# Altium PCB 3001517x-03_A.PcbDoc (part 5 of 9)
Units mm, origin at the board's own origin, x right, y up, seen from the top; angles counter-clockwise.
Board outline 100 x 72 mm, 10 copper layers (Top, GND_2, Signal_3, Signal_4, PWR_5, GND_6, Signal_7, Signal_8, GND_9, Bottom), stack 1.6 mm thick; 602 components, 497 nets, 2372 pads, 1602 vias.
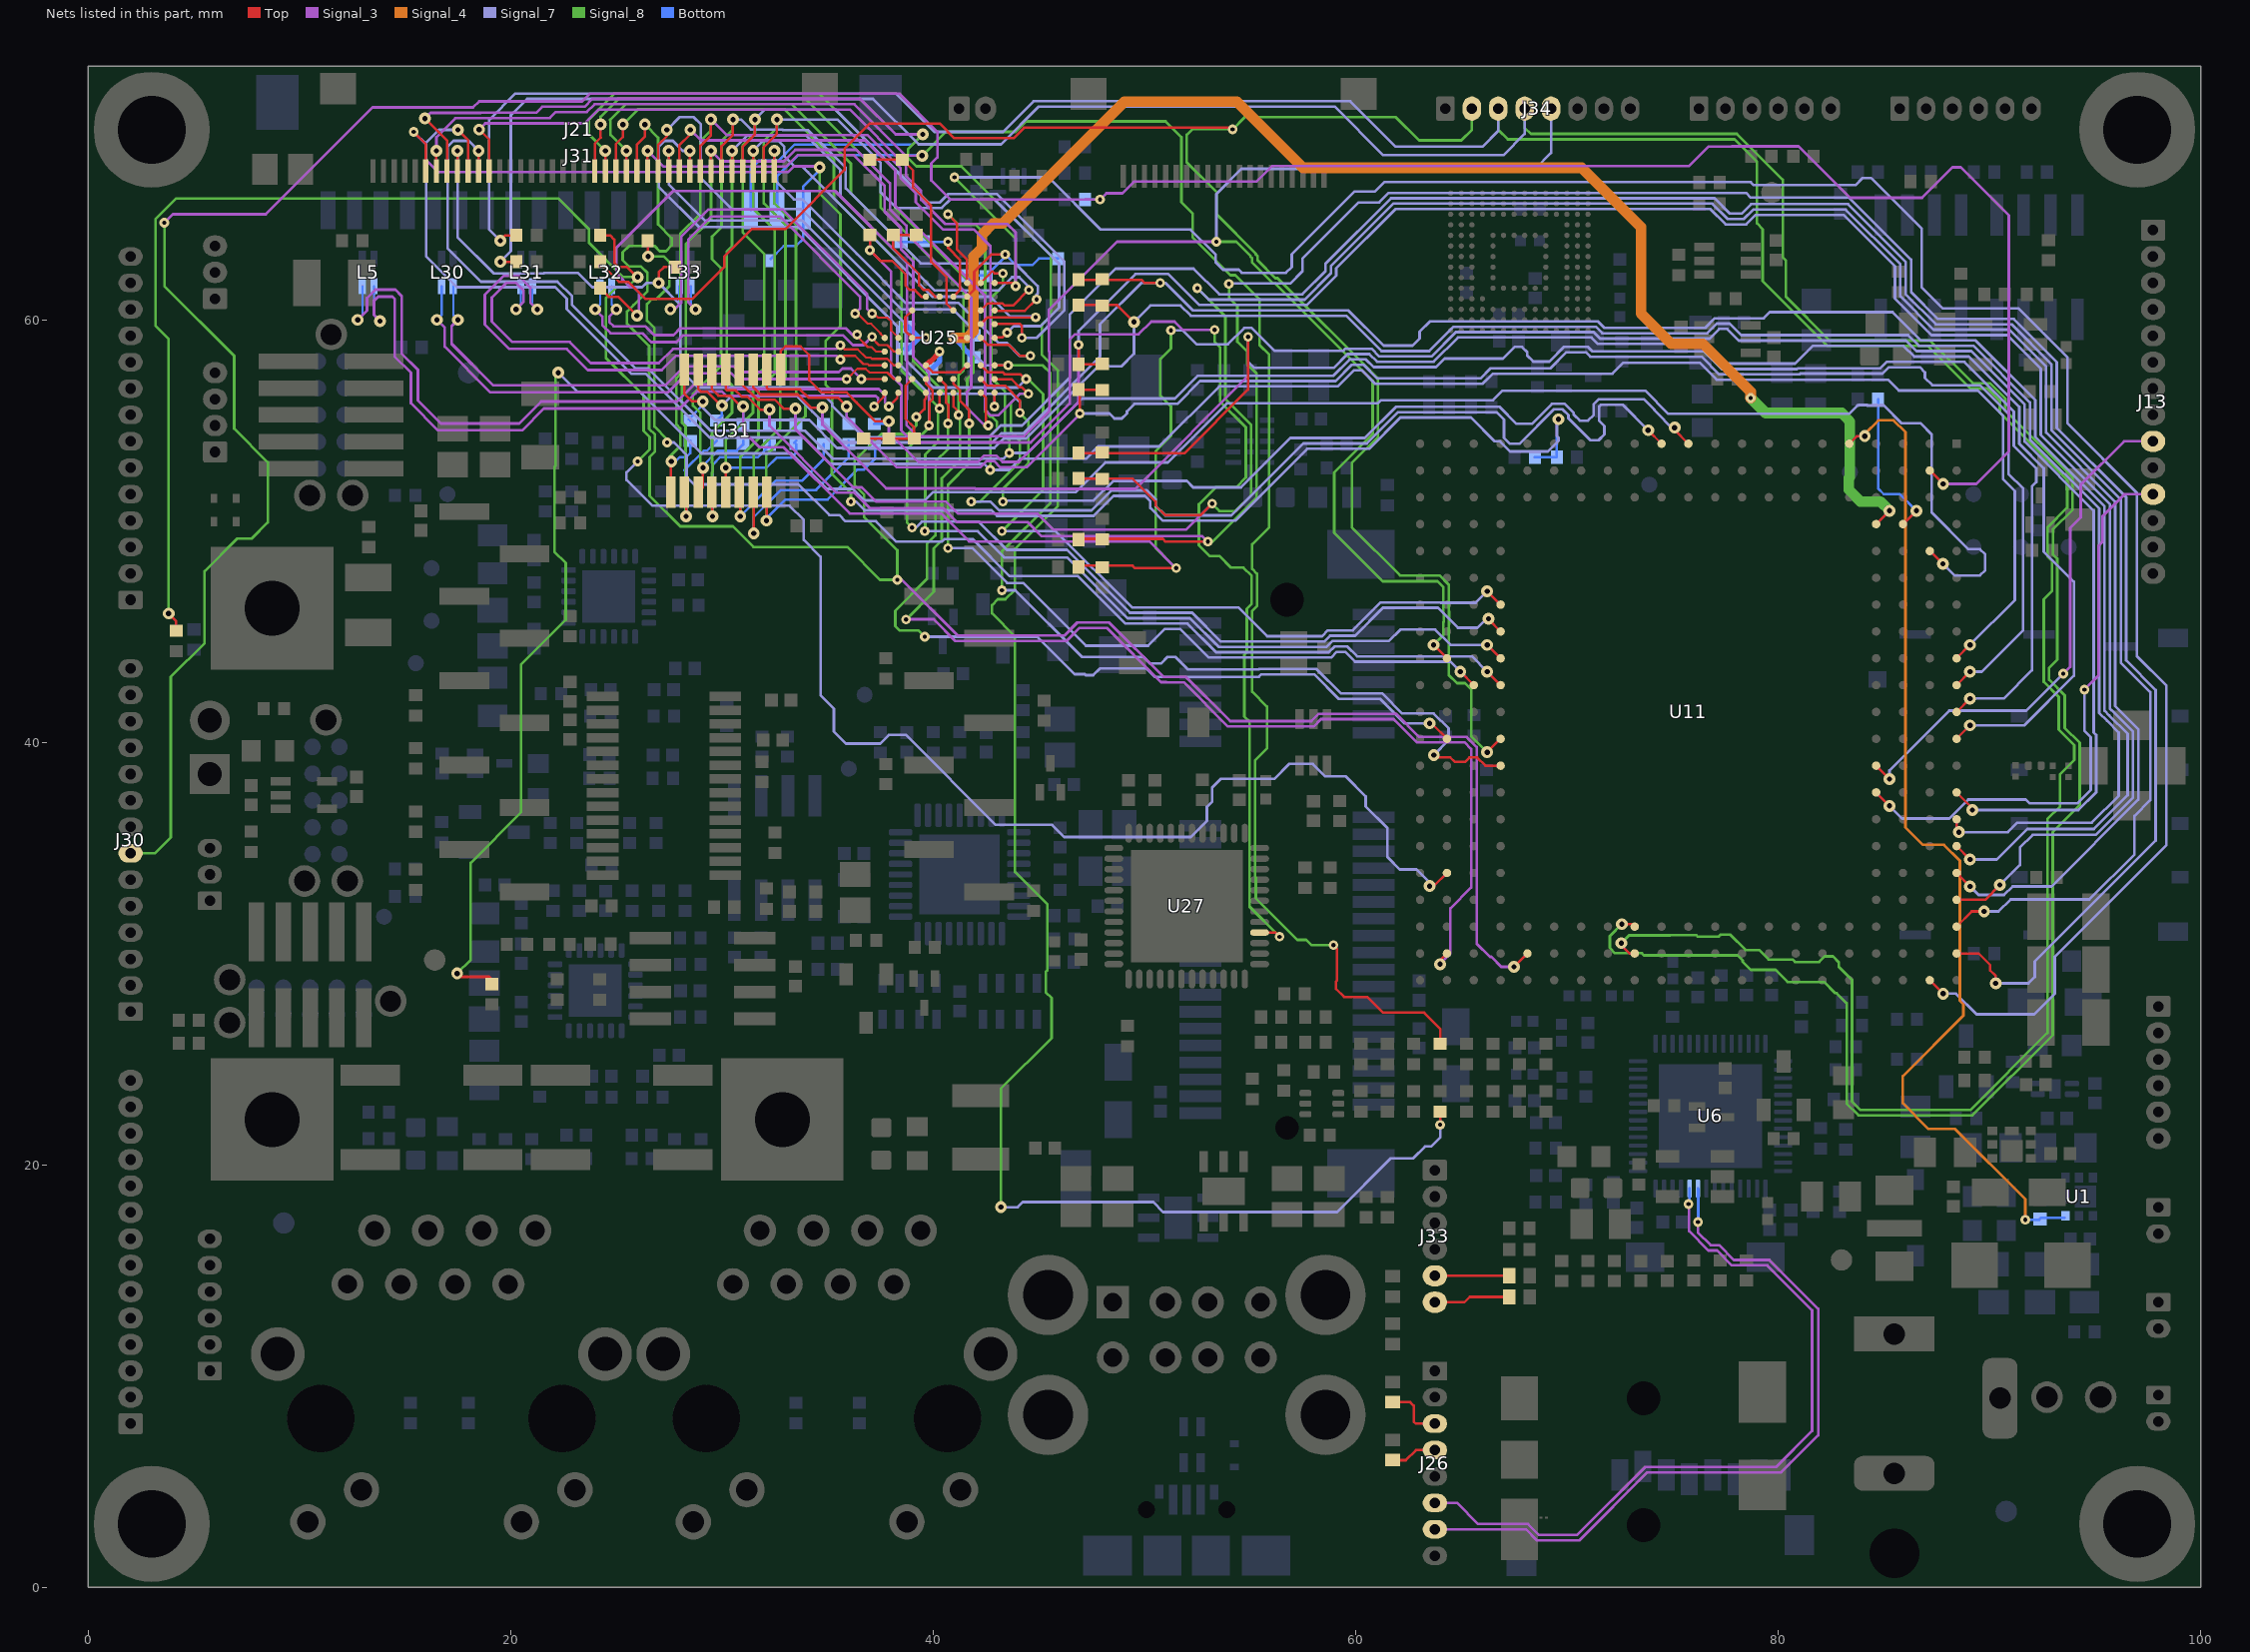
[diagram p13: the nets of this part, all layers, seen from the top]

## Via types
v1: diameter 0.56, hole 0.25, Top to Bottom, tented both sides, 1002 vias
v2: diameter 0.46, hole 0.2, Top to Bottom, tented both sides, 468 vias
v3: diameter 0.457, hole 0.2, Top to Bottom, tented both sides, 132 vias

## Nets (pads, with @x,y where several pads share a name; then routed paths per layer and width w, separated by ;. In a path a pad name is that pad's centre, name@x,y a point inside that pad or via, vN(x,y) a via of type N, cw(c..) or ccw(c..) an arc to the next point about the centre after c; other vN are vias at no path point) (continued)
LCD_DATA0: R112.2 R214.1 R222.1 U11.A18 U31.2 | length 112.7
  Top w0.119: U31.2@32.775,57.65 32.775,58.525 33,58.75 33.713,58.75 34.125,58.338 34.125,57.149 34.712,56.562 35.897,56.562 36.366,56.093 37.26,55.2 v1(37.9,55.2) ; v2(46.88,58.82) R222.1@46.88,57.9 47.98,57.9 R112.2@48,57.92 ; U11.A18@88.45,32.55 89.8,32.55 v1(90.5,33.25)
  Signal_3 w0.127: v1(37.9,55.2) 37.9,54.671 39.297,53.274 42.121,53.274 42.421,53.575 42.979,53.575 43.279,53.274 44.05,53.274 46.88,56.105 v2(46.88,58.82)
  Signal_7 w0.127: v2(46.88,58.82) 46.88,59.48 49.571,62.171 51.13,62.171 52.597,60.703 57.687,60.703 59.079,62.095 59.079,62.445 61.884,65.25 76.779,65.25 77.508,64.522 78.483,64.522 78.932,64.97 83.095,64.97 85.53,62.535 85.53,61.009 87.256,59.282 90.84,59.282 92.431,57.691 92.431,54.559 95.705,51.285 95.705,41.602 95.779,41.528 95.784,41.528 96.8,40.513 96.8,37.397 95.028,35.625 92.06,35.625 91.45,35.015 91.45,34.2 v1(90.5,33.25)
  Bottom w0.119: R214.1@37.208,55.08 37.88,55.08 37.9,55.1 v1(37.9,55.2)
LCD_DATA0_PROT: J21.2 R214.2 U25.H5 U31.18 | length 48.1
  Top w0.119: v1(32.1,50.5) 32.125,50.525 U31.18@32.125,51.85 ; J21.2@32.476,67.05 v1(32.476,68.007) ; U25.H5@42.25,59.15 42.575,58.825 43.571,58.825 44.096,58.3 v2(44.6,58.3)
  Signal_8 w0.127: v1(32.1,50.5) 32.1,53.6 33.945,55.445 33.945,55.995 33.504,56.436 33.504,59.62 33.496,59.628 33.496,64.504 32.476,65.524 v1(32.476,68.007)
  Signal_7 w0.127: v1(32.476,68.007) 32.476,66.624 33.4,65.7 33.8,65.7 36.374,63.126 38.7,60.8 41.2,60.8 43.08,58.92 43.476,58.92 44.096,58.3 v2(44.6,58.3)
  Bottom w0.119: v1(32.1,50.5) 32.1,50.6 33,51.5 35,51.5 36.415,52.915 36.715,52.915 37.25,53.45 R214.2@37.25,54.27
LCD_DATA1: R113.2 R215.1 R233.1 U11.A10 U31.3 | length 84.4
  Top w0.119: U31.3@32.125,57.65 U31.3@32.125,57.061 ; U31.3@32.173,57.013 U31.3@32.125,57.061 ; v1@36,55.8 v1(35.9,55.9) 35.484,56.316 34.091,56.316 33.694,56.713 32.187,56.713 32.125,56.775 U31.3@32.125,57.061 ; v2(46.935,55.565) 46.935,56.645 R233.1@46.88,56.7 47.98,56.7 R113.2@48,56.68 ; U11.A10@88.45,42.71 v1(89.085,43.345)
  Signal_3 w0.127: v1(35.9,55.9) 35.9,55.4 38.28,53.02 42.226,53.02 42.526,53.321 42.874,53.321 43.174,53.02 44.426,53.02 46.935,55.53 v2(46.935,55.565)
  Signal_7 w0.127: v2(46.935,55.565) 48.34,55.565 48.576,55.33 48.924,55.33 49.17,55.576 49.17,55.67 49.526,56.026 51.55,56.026 52.631,57.106 59.052,57.106 59.821,57.874 60.379,57.874 61.024,57.229 65.906,57.229 66.386,57.709 69.209,57.709 69.97,58.47 70.895,58.47 71.111,58.254 76.387,58.254 77.219,57.422 81.005,57.422 81.041,57.457 84.94,57.457 85.241,57.758 86.705,57.758 86.951,57.512 86.951,57.254 87.298,56.907 89.56,56.907 90.907,55.56 90.907,52.718 91.6,52.025 91.6,45.3 89.645,43.345 v1(89.085,43.345)
  Bottom w0.119: v1(35.9,55.9) 35.9,55.33 R215.1@36,55.23
LCD_DATA1_PROT: J21.3 R215.2 U25.J5 U31.17 | length 55.8
  Top w0.119: U31.17@31.475,51.85 31.5,51.825 v1(31.5,49.9) ; J21.3@31.976,67.05 31.976,68.181 32.599,68.804 v1(32.599,69.485) ; U25.J5@42.9,59.15 42.912,59.162 43.262,59.162 v2(43.5,59.4)
  Signal_8 w0.127: v1(31.5,49.9) 31.5,53.635 32.75,54.885 32.75,56.968 33,57.218 33,64.5 31.976,65.524 31.976,68.476 32.599,69.099 v1(32.599,69.485)
  Signal_7 w0.127: v1(32.599,69.485) 35.466,69.485 37.5,67.451 37.5,66.054 38.25,65.304 40.409,65.304 40.803,65.698 42.91,65.698 45.953,62.654 45.953,60.578 45.08,59.705 43.804,59.705 v2(43.5,59.4)
  Bottom w0.119: v1(31.5,49.9) 31.5,50.664 32.786,51.95 34.45,51.95 36,53.5 R215.2@36,54.12 R215.2@36,54.27
LCD_DATA2: R147.2 R216.1 R234.1 U11.A12 U31.4 | length 104.8
  Top w0.119: U31.4@31.475,57.65 31.475,56.821 31.828,56.467 33.592,56.467 34.21,55.85 v1(34.75,55.85) ; R234.1@46.88,53.7 51.906,53.7 54.9,56.694 v2(54.9,59.2) ; R147.2@48,53.72 R147.2@48.165,53.885 ; U11.A12@88.45,40.17 v1(89.085,40.805)
  Signal_3 w0.127: v1(34.75,55.85) 34.75,55.043 37.772,52.021 41.974,52.021 41.995,52 49.565,52 54.9,57.335 v2(54.9,59.2)
  Signal_7 w0.127: v2(54.9,59.2) 54.9,58.034 55.205,57.729 58.957,57.729 59.61,58.382 60.645,58.382 61.01,58.018 63.693,58.018 64.845,59.169 71.159,59.169 71.467,58.861 76.6,58.861 77.532,57.93 80.795,57.93 81.636,58.77 85.943,58.77 86.447,58.266 89.034,58.266 91.415,55.885 91.415,54.139 92.575,52.979 92.575,49.025 94,47.6 94,43.155 91.65,40.805 v1(89.085,40.805)
  Bottom w0.119: R216.1@34.75,55.23 v1(34.75,55.85)
LCD_DATA2_PROT: J21.4 R216.2 U25.H6 U31.16 | length 46.3
  Top w0.119: U31.16@30.825,51.85 30.863,51.812 v1(30.863,50.7) ; J21.4@31.476,67.05 v1(31.476,68.007) ; U25.H6@42.25,59.8 42.575,60.125 v2(44.85,60.125)
  Signal_8 w0.127: v1(30.863,50.7) 30.863,53.513 31.724,54.375 31.724,56.692 32.496,57.463 32.496,59.62 32.5,59.624 32.5,64.25 31.476,65.274 v1(31.476,68.007)
  Signal_7 w0.127: v1(31.476,68.007) 31.947,68.477 32.671,68.477 32.947,68.202 32.947,67.753 33.429,67.271 33.795,67.271 34.07,66.995 34.07,66.989 39.959,61.1 42.7,61.1 43.646,60.154 44.821,60.154 v2(44.85,60.125)
  Bottom w0.119: v1(30.863,50.7) 32.563,52.4 33.8,52.4 34.8,53.4 R216.2@34.8,54.12
LCD_DATA3: R153.2 R217.1 R235.1 U11.A17 U31.5 | length 128.2
  Top w0.119: U31.5@30.825,57.65 30.825,57.061 31.274,56.612 31.295,56.612 31.686,56.222 32.496,56.222 32.917,55.8 v1(33.475,55.8) ; R235.1@46.88,52.5 46.9,52.48 R153.2@48,52.48 49.444,52.48 50.533,51.391 50.533,51.207 50.99,50.75 52.65,50.75 v2(53.2,51.3) ; U11.A17@88.45,33.82 v1(89.085,33.185)
  Signal_3 w0.127: v1(33.475,55.8) 33.475,54.825 36.226,52.074 36.618,52.074 37.292,51.4 40.6,51.4 41.174,50.826 44.937,50.826 45.683,50.08 51.979,50.08 v2(53.2,51.3)
  Signal_8 w0.127: v2(52.5,61.5) 53.832,60.168 53.832,56.245 55.054,55.024 55.054,51.689 54.315,50.95 53.55,50.95 v2(53.2,51.3)
  Signal_7 w0.127: v2(52.5,61.5) 53.043,60.957 57.582,60.957 58.825,62.2 58.825,62.55 61.779,65.504 76.884,65.504 77.613,64.776 78.378,64.776 78.827,65.224 83.2,65.224 85.784,62.641 85.784,61.114 87.362,59.536 90.945,59.536 92.685,57.797 92.685,54.665 95.959,51.39 95.959,41.713 97.054,40.618 97.054,37.68 97.054,37.291 92.948,33.185 91.1,33.185 90.695,32.78 89.491,32.78 v1(89.085,33.185)
  Bottom w0.119: v1(33.475,55.8) 33.475,55.255 R217.1@33.5,55.23
LCD_DATA3_PROT: J21.5 R217.2 U25.J6 U31.15 | length 50.8
  Top w0.119: U31.15@30.175,51.85 v1(30.175,53.007) ; J21.5@30.976,67.05 30.976,68.202 31.558,68.783 v1(31.558,69.485) ; U25.J6@42.9,59.8 42.917,59.816 44.084,59.816 44.2,59.7 v2(44.2,59.15)
  Signal_8 w0.127: v1(30.175,53.007) 30.175,54.31 31.47,55.605 31.47,57.22 32,57.75 32,63.118 30.976,64.142 30.976,68.274 31.558,68.855 v1(31.558,69.485)
  Signal_7 w0.127: v1(31.558,69.485) 32.028,69.956 35.355,69.956 39.753,65.558 40.304,65.558 40.698,65.952 43.016,65.952 46.207,62.76 46.207,60.467 44.891,59.15 v2(44.2,59.15)
  Bottom w0.119: v1(30.175,53.007) 32.115,53.007 32.582,53.473 33.276,53.473 33.5,53.697 R217.2@33.5,54.12 ; R217.2@33.425,54.195 R217.2@33.5,54.27
LCD_DATA4: R17.1 R218.1 R238.2 U11.A20 U31.6 | length 131.8
  Top w0.119: U31.6@30.175,57.65 30.175,56.725 30.241,56.659 30.641,56.659 30.933,56.366 31.193,56.366 31.81,55.75 v1(32.25,55.75) ; R17.1@46.88,49.6 46.915,49.635 50.865,49.635 51,49.5 v2(53,49.5) ; U11.A20@88.45,30.01 89.49,30.01 90.034,29.466 90.034,29.207 90.3,28.94 v1(90.3,28.6)
  Signal_3 w0.127: v1(32.25,55.75) 32.25,54.993 35.423,51.82 36.274,51.82 37.005,51.089 40.474,51.089 41.143,50.42 44.48,50.42 45.136,49.764 52.736,49.764 v2(53,49.5)
  Signal_8 w0.127: v2(53,49.5) 53.225,49.5 55.308,51.583 55.308,57.457 54.87,57.895 54.87,58.495 54.4,58.965 54.4,60.654 54,61.054 v2(54,61.7)
  Signal_7 w0.127: v2(54,61.7) 54,61.625 54.096,61.721 56.905,61.721 57.478,62.295 57.478,62.894 60.147,65.562 61.118,65.562 61.568,66.012 78.488,66.012 78.708,65.792 83.351,65.792 86.292,62.851 86.292,61.324 87.572,60.044 91.156,60.044 93.193,58.007 93.193,54.893 96.477,51.609 96.477,43.88 97.875,42.481 97.875,35.351 92.152,29.627 92.152,28.898 91.853,28.6 v1(90.3,28.6)
  Bottom w0.119: R218.1@32.25,55.03 v1(32.25,55.75)
LCD_DATA4_PROT: J21.6 R218.2 U25.H7 U31.14 | length 47.3
  Top w0.119: U31.14@29.525,51.85 29.55,51.825 v1(29.55,50.7) ; J21.6@30.476,67.05 v1(30.476,68.007) ; U25.H7@42.25,60.45 42.589,60.789 43.272,60.789 43.377,60.684 43.784,60.684 v2(44.525,61.425)
  Signal_8 w0.127: v1(29.55,50.7) 29.529,50.721 29.529,52.764 29.57,52.805 29.57,53.195 29.529,53.236 29.529,54.664 30.47,55.605 30.47,55.752 ; 30.471,55.752 30.471,56.904 30.225,57.15 30.225,63.225 30.476,63.476 v1(30.476,68.007)
  Signal_7 w0.127: v1(30.476,68.007) 31.201,68.731 33.969,68.731 35.6,67.1 35.6,65.855 40.055,61.4 43.105,61.4 43.726,62.02 44.074,62.02 44.525,61.569 v2(44.525,61.425)
  Bottom w0.119: v1(29.55,50.7) 29.566,50.716 29.566,53.166 29.9,53.5 31.7,53.5 32.25,54.05 R218.2@32.25,54.27
LCD_DATA5: R156.2 R219.1 R236.1 U11.A14 U31.7 | length 116.2
  Top w0.119: U31.7@29.7,57.475 U31.7@29.525,57.65 29.525,56.715 29.827,56.413 30.387,56.413 30.9,55.9 v1(31,55.9) ; R236.1@46.88,48.3 46.88,48.4 46.9,48.38 48,48.38 48.015,48.365 49.44,48.365 49.555,48.25 v2(51.5,48.25) ; U11.A14@88.45,37.63 89.2,36.88 v1(89.2,36.8)
  Signal_3 w0.127: v1(31,55.9) 31,54.75 31.777,53.973 32.911,53.973 36.048,50.835 40.368,50.835 41.694,49.51 50.24,49.51 v2(51.5,48.25)
  Signal_8 w0.127: v2(51.25,59.5) 51.25,58.65 50.75,58.15 50.75,56.408 51.25,55.908 51.25,54.503 50.529,53.782 50.529,49.221 v2(51.5,48.25)
  Signal_7 w0.127: v2(51.25,59.5) 51.811,59.5 52.464,58.847 53.952,58.847 54.726,59.62 55.074,59.62 56.165,58.529 59.398,58.529 59.505,58.636 60.75,58.636 61.115,58.272 63.588,58.272 64.739,59.423 71.264,59.423 71.572,59.115 76.75,59.115 77.205,59.571 77.595,59.571 78.141,59.024 86.048,59.024 86.552,58.52 89.139,58.52 91.669,55.99 91.669,54.244 94.943,50.97 94.943,40.462 95.054,40.351 95.054,37.637 94.217,36.8 v1(89.2,36.8)
  Bottom w0.119: R219.1@31,55.23 v1(31,55.9)
LCD_DATA5_PROT: J21.7 R219.2 U25.J7 U31.13 | length 45.3
  Top w0.119: U31.13@28.875,51.85 29.1,52.075 v1(29.1,53) ; J21.7@29.976,67.05 29.976,68.222 30.516,68.762 v1(30.516,69.485) ; U25.J7@42.9,60.45 42.913,60.438 44.338,60.438 44.866,60.966 v2(44.896,60.966)
  Signal_8 w0.127: v1(29.1,53) 29,53 28.975,53.025 28.975,55.592 28.621,55.946 28.621,56.496 29.95,57.825 29.95,62.45 29.53,62.87 29.53,63.945 29.976,64.392 29.976,68.476 30.516,69.016 v1(30.516,69.485)
  Signal_7 w0.127: v1(30.516,69.485) 30.892,69.485 31.363,69.015 32.853,69.015 32.882,68.985 34.074,68.985 35.854,67.205 35.854,66.23 39.405,62.68 43.865,62.68 44.946,61.599 44.946,61.251 44.896,61.201
  Bottom w0.119: v1(29.1,53) 29.1,53.1 29.795,53.795 30.695,53.795 31,54.1 R219.2@31,54.12 R219.2@31,54.27
LCD_DATA6: R166.2 R220.1 R237.1 U11.A16 U31.8 | length 108.6
  Top w0.119: U31.8@28.875,57.65 28.875,56.737 29.004,56.608 29.285,56.608 v1@29.946,55.947 ; R237.1@46.88,61.9 49.85,61.9 50,61.75 v2(50.75,61.75) ; U11.A16@88.45,35.09 v1(89.085,34.455)
  Signal_7 w0.127: v1(30,55.947) 30.453,56.4 33.54,56.4 34.28,55.661 34.28,55.655 34.555,55.379 34.561,55.379 35.744,54.196 42.786,54.196 43.216,54.626 44.267,54.626 47.9,58.26 47.9,59.8 49.85,61.75 v2(50.75,61.75) 50.995,61.75 52.296,60.449 59.656,60.449 61.326,58.78 62.695,58.78 63.03,59.114 63.03,59.445 63.516,59.931 71.474,59.931 71.782,59.623 76.539,59.623 76.995,60.079 79.313,60.079 79.605,60.37 85.42,60.37 86.763,59.028 89.349,59.028 92.177,56.201 92.177,54.454 95.451,51.18 95.451,41.497 95.674,41.274 95.679,41.274 96.546,40.408 96.546,37.502 94.944,35.9 91.8,35.9 90.355,34.455 v1(89.085,34.455)
  Bottom w0.119: R220.1@29.75,55.23 30,55.48 v1(30,55.947)
LCD_DATA6_PROT: J21.8 R220.2 U25.H1 U31.12 | length 49.7
  Top w0.119: U31.12@28.225,51.85 28.3,51.775 v1(28.3,50.7) ; J21.8@29.476,67.05 v1(29.476,68.007) ; U25.H1@42.25,56.55 42.484,56.316 v2@42.484,55 ; v2(42.6,55) v2@42.484,55 ; v2@42.484,55 42.484,54.916 42.4,55 v2@42.484,55
  Signal_3 w0.127: v1(29.476,68.007) 29.975,67.508 32.925,67.508 33.47,68.053 36.358,68.053 37.948,66.463 37.948,65.236 38.729,64.455 38.729,64.105 41.8,61.034 41.8,56.8 41.6,56.6 41.6,55.833 42.433,55 v2(42.6,55)
  Signal_8 w0.127: v1(28.3,50.7) 28.275,50.725 28.275,54.969 28.099,55.145 28.099,57.145 28.28,57.326 28.28,63.58 29.476,64.777 v1(29.476,68.007)
  Bottom w0.119: v1(28.3,50.7) 28.3,52.814 28.225,52.889 29.136,53.8 29.28,53.8 R220.2@29.75,54.27
LCD_DATA7: R100.1 R221.1 R239.2 U11.A15 U31.9 | length 106.5
  Top w0.119: U31.9@28.225,57.65 28.225,56.5 28.584,56.141 v1(29.092,56.141) ; R100.1@46.88,60.7 48.7,60.7 v1(49.5,59.9) ; U11.A15@88.45,36.36 88.45,35.856 v1(88.554,35.752) v1@88.562,35.752
  Signal_7 w0.127: v1(29.092,56.141) 29.092,55.835 29.668,55.259 34.13,55.259 35.447,53.942 42.891,53.942 43.321,54.372 44.372,54.372 47.8,57.8 48.9,57.8 49.5,58.4 v1(49.5,59.9) 50.281,60.681 51.705,60.681 52.19,60.195 59.551,60.195 61.221,58.526 63.482,58.526 64.634,59.677 71.369,59.677 71.677,59.369 76.645,59.369 77.1,59.825 77.7,59.825 78.246,59.278 86.153,59.278 86.657,58.774 89.244,58.774 91.923,56.095 91.923,54.349 95.197,51.075 95.197,41.392 95.568,41.02 95.574,41.02 96.125,40.469 96.125,37.47 94.855,36.2 91.318,36.2 90.87,35.752 v1(88.554,35.752)
  Bottom w0.119: R221.1@28.5,55.23 28.43,55.299 29.092,55.961 v1(29.092,56.141)
LCD_DATA7_PROT: J21.9 R221.2 U25.J1 U31.11 | length 47.7
  Top w0.119: U31.11@27.575,51.85 27.575,53.075 27.7,53.2 v1(27.6,53.3) ; J21.9@28.976,67.05 28.976,68.243 29.475,68.742 v1(29.475,69.485) ; v2(42.9,55.9) U25.J1@42.9,56.55
  Signal_3 w0.127: v1(29.475,69.485) 30.206,68.754 36.88,68.754 38.456,67.177 38.456,66.709 39.17,65.995 39.17,65.575 40.46,64.286 41.914,64.286 42.7,63.5 42.7,57 42.9,56.8 v2(42.9,55.9)
  Signal_8 w0.127: v1(27.6,53.3) 27.6,53.4 27.5,53.5 28.021,54.02 28.021,54.864 27.845,55.04 27.845,57.251 28.026,57.432 28.026,64.073 28.976,65.024 28.976,68.476 29.475,68.975 v1(29.475,69.485)
  Bottom w0.119: v1(27.6,53.3) 27.7,53.2 28,53.5 28.3,53.5 28.5,53.7 R221.2@28.5,54.27
LCD_DATA8: J21.10 U11.L1 U25.H2 | length 72.8
  Top w0.119: J21.10@28.476,67.05 v1(28.476,68.007) ; U25.H2@42.25,57.2 42.575,56.875 43.422,56.875 44.1,56.197 v2(44.1,55.6) ; v1(75.1,54.9) 75.1,54.79 U11.L1@75.75,54.14
  Signal_8 w0.127: v2(43.3,51.4) 43.3,51.892 43.25,51.942 44.5,53.192 44.5,55.2 v2(44.1,55.6)
  Signal_7 w0.127: v1@28.476,68.032 v1(28.476,68.007) 28.142,68.007 27.671,68.477 27.281,68.477 27.006,68.202 27.006,66.295 28.9,64.4 33.595,64.4 38.3,59.695 38.3,58 39.8,56.5 43.72,56.5 44.1,56.12 v2(44.1,55.6) ; v2(43.3,51.4) 43.3,51.444 43.303,51.447 47.597,51.447 48.525,52.375 52,52.375 52.305,52.071 54.571,52.071 56.908,54.408 60.424,54.408 61.904,55.888 66.798,55.888 67.604,55.082 68.348,55.082 69.29,56.024 69.9,56.024 70.324,55.6 70.324,55.51 70.605,55.229 70.995,55.229 71.27,55.505 71.27,56.012 71.496,56.237 73.653,56.237 74.135,55.755 74.135,55.731 75.091,54.775 75.1,54.784 v1(75.1,54.9)
LCD_DATA9: J21.11 U11.M1 U25.J2 | length 78.3
  Top w0.119: J21.11@27.976,67.05 27.976,68.264 28.5,68.787 v1(28.5,69) ; U25.J2@42.9,57.2 42.912,57.188 43.712,57.188 44.1,56.8 44.2,56.8 v2(44.5,56.5) ; v1(73.845,54.775) U11.M1@74.48,54.14
  Signal_3 w0.127: v1(28.5,69) 29,68.5 36.774,68.5 38.202,67.072 38.202,65.398 42.446,61.154 42.446,56.895 42.46,56.881 42.46,55.745 42.726,55.48 43.074,55.48 44.095,56.5 v2(44.5,56.5)
  Signal_8 w0.127: v2(41.8,51.4) 42.22,51.4 44.1,53.279 44.1,54.272 43.68,54.693 43.68,56.079 44.1,56.5 v2(44.5,56.5)
  Signal_7 w0.127: v2(41.8,51.4) 42.705,51.4 43.126,50.979 47.488,50.979 48.434,51.924 50.123,51.924 50.529,51.518 50.529,51.205 50.984,50.75 54.115,50.75 57.519,54.154 60.529,54.154 62.009,55.634 66.674,55.634 67.025,55.283 67.025,54.416 67.308,54.132 67.757,54.132 69.395,55.77 69.795,55.77 70.07,55.495 70.07,55.344 71.11,54.305 71.5,54.305 71.776,54.58 71.776,54.97 71.525,55.22 71.525,55.908 71.601,55.983 72.637,55.983 v1(73.845,54.775)
LCD_DATA10: J21.12 U11.V7 U25.H3 | length 62.2
  Top w0.119: J21.12@27.476,67.05 v1(27.476,68.007) ; U25.H3@42.25,57.85 42.575,57.525 43.286,57.525 43.377,57.434 44.109,57.434 44.342,57.2 v2(44.4,57.2) ; v1(66.225,47.155) U11.V7@66.86,46.52
  Signal_8 w0.127: v2(43.25,50) 45.2,51.95 45.2,56.494 44.495,57.2 v2(44.4,57.2)
  Signal_7 w0.127: v1(27.476,68.007) 27.476,66.424 29.2,64.7 33.8,64.7 38.7,59.8 38.7,58.1 40,56.8 44,56.8 v2(44.4,57.2) ; v2(43.25,50) 45.8,50 49.414,46.386 54.448,46.386 55.805,45.029 58.412,45.029 58.684,45.302 59.861,45.302 61.184,46.624 64,46.624 64.015,46.61 65.68,46.61 v1(66.225,47.155)
LCD_DATA11: J21.13 U11.V13 U25.J3 | length 68.8
  Top w0.119: J21.13@26.976,67.05 26.976,68.285 27.392,68.7 v1(27.392,69) ; U25.J3@42.9,57.85 v2(43.55,57.85) ; v1(63.7,39.4) 63.813,39.287 64.48,39.287 64.698,39.069 65.169,39.069 65.386,39.287 65.75,39.287 66.137,38.9 U11.V13@66.86,38.9
  Signal_8 w0.127: v2(43.25,47.2) 43.25,49.05 45.546,51.346 45.546,57.479 45.175,57.85 v2(43.55,57.85)
  Signal_7 w0.127: v1(27.392,69) 27.992,69.6 28.652,69.6 29,69.252 29,66.7 30.446,65.254 33.746,65.254 38.508,60.492 40.954,60.492 41.9,59.546 41.9,58.4 42.45,57.85 v2(43.55,57.85) ; v2(43.25,47.2) 43.887,47.2 47.043,44.043 49.957,44.043 50.266,43.734 50.772,43.734 51.082,44.043 51.471,44.043 52.069,43.446 55.405,43.446 55.434,43.474 58.144,43.474 59.307,42.312 61.268,42.312 62.209,41.37 63.695,41.37 64.4,40.665 64.4,40.1 v1(63.7,39.4)
LCD_DATA12: J21.14 U11.V8 U25.D2 | length 65.3
  Top w0.119: J21.14@26.476,67.05 v1(26.476,68.007) ; U25.D2@39.65,57.2 39.65,56.99 39.961,56.679 39.961,56.239 39.825,56.103 39.825,54.925 39.8,54.95 v2(39.8,55) ; v1@66.285,45.825 U11.V8@66.86,45.25
  Signal_3 w0.127: v1(26.476,68.007) 27.229,67.254 33.03,67.254 33.575,67.799 36.251,67.799 37.694,66.356 37.694,65.131 38.475,64.35 38.475,63.339 39.054,62.761 39.054,58.246 39.8,57.5 v2(39.8,55)
  Signal_8 w0.127: v2(39,50.163) 38.758,50.405 38.758,53.858 39.8,54.9 v2(39.8,55)
  Signal_7 w0.127: v2(39,50.163) 39.163,50.163 39.446,50.446 42.154,50.446 43.487,49.113 46.328,49.113 49.308,46.132 52.258,46.132 53.615,44.775 58.517,44.775 58.789,45.048 59.966,45.048 61.289,46.37 63.895,46.37 64.836,45.429 65.769,45.429 66.24,45.9 v1(66.285,45.855)
LCD_DATA13: J21.15 U11.U20 U25.D1 | length 93.8
  Top w0.119: J21.15@25.976,67.05 25.976,68.305 26.351,68.679 v1(26.351,69.25) ; v2(39.2,55.4) 39.579,55.779 39.579,56.205 39.65,56.276 U25.D1@39.65,56.55 ; v1(67.495,29.375) U11.U20@68.13,30.01
  Signal_3 w0.127: v2(38.3,47.7) 38.509,47.7 41.148,45.061 46.207,45.061 46.821,45.674 48.32,45.674 50.892,43.102 51.136,43.102 51.139,43.1 51.965,43.1 54.058,41.007 57.904,41.007 58.252,41.354 61.905,41.354 63,40.26 65.255,40.26 65.73,39.785 65.73,30.475 66.359,29.846 66.42,29.846 66.89,29.375 v1(67.495,29.375)
  Signal_8 w0.127: v1(26.351,69.25) 26.976,68.624 26.976,64.518 27.62,63.874 27.62,63.526 27.349,63.254 27.046,63.254 26.8,63.5 25.6,63.5 25.3,63.2 25.3,62.834 25.605,62.529 26.165,62.529 26.472,62.223 26.472,61.833 26.47,61.832 26.47,61.351 25.824,60.705 25.814,60.705 25.505,60.395 25.505,59.811 26.546,58.77 26.546,54.845 26.826,54.565 26.826,53.769 26.827,53.768 26.574,53.515 26.574,51.676 28.027,50.223 30.512,50.223 31.485,49.25 35.925,49.25 37.475,47.7 v2(38.3,47.7) 38.3,49.1 36.72,50.68 36.72,51.73 36.281,52.17 36.281,53.34 37.541,54.6 38.8,54.6 39.2,55 v2(39.2,55.4)
LCD_DATA14: J21.16 U11.Y12 U25.E2 | length 72
  Top w0.119: J21.16@25.476,67.05 v1(25.476,68.007) ; U25.E2@40.3,57.2 40.611,56.889 40.611,56.078 40.716,55.973 40.716,54.916 40.7,54.933 v2(40.7,55.1) ; v1(63.5,40.9) 63.59,40.9 U11.Y12@64.32,40.17
  Signal_8 w0.127: v1(25.476,68.007) 24.72,68.763 24.72,69.445 24.7,69.465 25.451,70.216 33.283,70.216 36.1,67.4 36.1,65.984 39.054,63.03 39.054,58.046 40.721,56.38 40.721,55.12 v2(40.7,55.1) v2@40.7,54.941 ; v2(39.6,45) 39.3,45.3 38.4,45.3 38.2,45.5 38.2,46.232 39.7,47.732 39.7,49.4 40.1,49.8 40.1,53.3 40.7,53.9 v2@40.7,54.941 ; v2@40.721,55.1 40.721,54.92 v2@40.7,54.941
  Signal_7 w0.127: v2(39.6,45) 44.925,45 46.7,43.225 47.18,43.225 47.226,43.179 47.574,43.179 47.895,43.5 50.085,43.5 50.482,43.102 55.421,43.102 55.539,43.22 58.039,43.22 59.202,42.058 61.162,42.058 62.32,40.9 v1(63.5,40.9)
LCD_DATA15: J21.17 U11.V9 U25.E1 | length 64.8
  Top w0.119: J21.17@24.976,67.05 24.976,68.326 25.309,68.659 v1(25.309,69.25) ; v2(40.3,55.8) U25.E1@40.3,56.55 ; v1(66.225,44.615) U11.V9@66.86,43.98
  Signal_8 w0.127: v1(25.309,69.25) 26.022,69.962 32.947,69.962 35.3,67.609 35.3,65.759 38.5,62.559 38.5,57.6 v2(40.3,55.8) 40.22,55.72 40.22,54.22 39.62,53.62 39.62,50.02 v2(39.6,50)
  Signal_7 w0.127: v2(39.6,50) 42.1,50 43.35,48.75 46.332,48.75 49.203,45.878 52.153,45.878 53.51,44.521 58.622,44.521 58.895,44.794 61.569,44.794 62.115,45.34 63.76,45.34 64.485,44.615 v1(66.225,44.615)
LCD_DATA16: J21.18 U11.W10 U25.F2 | length 70.2
  Top w0.119: J21.18@24.476,67.05 v1(24.476,68.007) ; U25.F2@40.95,57.2 40.95,56.99 41.261,56.679 41.261,56.178 41.7,55.739 v2(41.7,55.1) ; v1(64.955,43.345) U11.W10@65.59,42.71
  Signal_8 w0.127: v1(24.476,68.007) 23.7,68.783 23.7,69.5 24.924,70.724 34.586,70.724 38.2,67.11 38.2,65.3 41.9,61.6 41.9,57.5 41.606,57.206 41.606,55.827 41.7,55.733 v2(41.7,55.1) 41.7,53.2 40.7,52.2 v2(40.7,49.2)
  Signal_7 w0.127: v2(40.7,49.2) 41.845,49.2 43.495,47.55 44.255,47.55 47.226,44.579 50.17,44.579 50.961,45.37 51.689,45.37 53.046,44.013 58.833,44.013 59.105,44.286 59.495,44.286 59.965,43.816 64.485,43.816 v1(64.955,43.345)
LCD_DATA17: J21.19 U11.Y20 U25.F1 | length 84.5
  Top w0.119: J21.19@23.976,67.05 23.976,68.347 24.268,68.638 24.25,68.656 v1(24.25,69.25) ; U25.F1@40.95,56.55 40.962,56.538 40.962,55.888 41.2,55.65 v2(41.2,55.5) ; v1(64,29.5) 64,29.69 U11.Y20@64.32,30.01
  Signal_3 w0.127: v2@38.7,45.8 v2(38.713,45.813) 38.726,45.826 40.024,45.826 41.05,44.8 46.305,44.8 46.926,45.42 48.215,45.42 50.787,42.848 51.031,42.848 51.034,42.846 51.86,42.846 53.953,40.753 58.009,40.753 58.357,41.1 61.8,41.1 62.894,40.006 65.15,40.006 65.47,39.685 65.47,33.136 64.485,32.15 64.485,30.02 63.965,29.5 v1(64,29.5)
  Signal_8 w0.127: v1(24.25,69.25) 24.25,69.614 25.107,70.47 33.941,70.47 37.5,66.912 37.5,65.325 41.431,61.395 41.431,57.614 41.2,57.383 v2(41.2,55.5) v2@41.271,55.571 ; v2(38.713,45.813) 40.026,47.126 40.026,49.181 40.4,49.555 40.4,52.5 41.271,53.371 v2@41.271,55.5
LCD_DATA18: R41.1 U11.V10 | length 56.5
  Top w0.119: R41.1@26.48,63.75 26.5,63.73 v1(26.5,63) ; v1(66.225,43.345) U11.V10@66.86,42.71
  Signal_8 w0.127: v1(26.5,63) 27.25,63 27.5,62.75 27.5,61.585 26.915,61 26.7,61 26.445,60.745 26.445,59.96 26.8,59.605 26.8,54.95 27.4,54.35 v2(27.4,54.2)
  Signal_7 w0.125: v2(27.4,54.2) 27.725,54.2 28.2,53.724
  Signal_7 w0.127: 28.2,53.724 28.324,53.6 28.324,52.566 28.675,52.216 33.621,52.216 35.076,50.761 35.56,50.761 35.85,50.47 37.28,50.47 38.25,49.5 40.405,49.5 40.526,49.621 41.879,49.621 43.628,47.872 46.85,47.872 49.098,45.624 52.035,45.624 53.392,44.267 58.727,44.267 59,44.54 59.6,44.54 60.071,44.07 65.501,44.07 v1(66.225,43.345)
LCD_DATA19: R207.1 R256.2 U11.Y17 | length 117.4
  Top w0.119: v1(3.8,46.1) 4.158,45.742 R256.2@4.158,45.28 ; R207.1@24.23,64 24.7,64 24.9,63.8 24.9,62.7 25.1,62.5 25.5,62.5 25.972,62.028 v1(26.001,62.028) ; v1(63.5,33.2) 63.7,33.2 U11.Y17@64.32,33.82
  Signal_8 w0.127: v1(3.8,46.1) 3.8,59.1 3.18,59.721 3.18,64.774 4.155,65.75 22.25,65.75 23.7,64.3 23.7,63.656 25.328,62.028 v1(26.001,62.028) 25.519,61.546 25.015,61.546 24.5,61.03 24.5,58.205 26.292,56.413 26.292,54.74 26.572,54.46 26.572,53.872 v2(26,53.3)
  Signal_7 w0.127: v2(26,53.3) 25.479,52.78 25.479,52.774 25.479,52.426 26.705,51.2 33.2,51.2 33.867,50.533 33.867,49.589 34.663,48.793 34.663,42.231 35.3,41.595 35.3,40.518 35.872,39.946 37.492,39.946 37.896,40.35 38.714,40.35 42.963,36.1 45.625,36.1 46.204,35.521 52.19,35.521 52.955,36.286 52.955,36.945 53.208,37.198 53.208,37.873 53.606,38.271 56.138,38.271 56.845,38.978 57.965,38.978 58.544,38.4 59.515,38.4 60.47,37.445 60.47,36.97 61.501,35.94 61.501,34.573 62.089,33.985 62.886,33.985 63.5,33.37 v1(63.5,33.2)
LCD_DATA20/SPI1_CLK: J34.2 R208.1 U11.V12 | length 89.5
  Top w0.119: R208.1@24.23,62.75 24.23,62.695 25.119,61.806 25.558,61.806 26.364,61 28.6,61 30.1,62.5 30.1,63 31.4,64.3 33,64.3 35.8,67.1 35.8,68.1 37,69.3 40.3,69.3 41,68.6 43.8,68.6 44.3,69.1 54.1,69.1 v2(54.175,69.025) ; v1(66.225,39.535) U11.V12@66.86,40.17
  Signal_8 w0.127: J34.2@65.5,70 65.5,69 65,68.5 63,68.5 61.9,69.6 54.75,69.6 v2(54.175,69.025) 52.273,69.025 52.004,68.756 52.004,67.448 53.419,66.032 53.419,64.99 55.276,63.134 55.276,63.1 55.354,63.021 55.354,62.821 56.2,61.975 56.299,61.975 61.054,57.221 61.054,54.454 59.821,53.221 59.821,50.18 62.1,47.9 63.965,47.9 64.41,47.455 64.41,46.215 64.424,46.2 64.424,45.6 64.41,45.585 64.41,43.191 64.8,42.8 65.177,42.8 65.477,42.5 65.477,40.283 v1(66.225,39.535)
LCD_DATA21/SPI1_SS0: J34.5 R209.1 U11.Y9 | length 100.9
  Top w0.119: R209.1@24.23,61.5 24.63,61.1 25.075,61.1 v1(25.975,60.2) ; v1(63.685,44.615) U11.Y9@64.32,43.98
  Signal_3 w0.127: v1(25.975,60.2) 26.07,60.295 26.07,61.299 25.824,61.546 25.654,61.546 25,62.2 25,63.423 27.677,66.1 35.355,66.1 38.754,62.701 38.754,56.249 38.742,56.237 38.742,55.009 39.251,54.5 44.3,54.5 45.5,55.7 45.5,58.505 45.479,58.526 45.479,60.479 48.7,63.7 v2(53.4,63.7)
  Signal_8 w0.127: v2(53.4,63.7) 54.35,63.7 55.022,63.029 55.022,62.995 55.1,62.916 55.1,62.716 56.095,61.721 56.194,61.721 60.8,57.115 60.8,54.6 58.98,52.78 58.98,49.92 61.274,47.626 63.88,47.626 64.156,47.35 64.156,46.11 64.17,46.095 64.17,45.705 64.156,45.69 64.156,45.086 v1(63.685,44.615)
  Signal_7 w0.127: v2(53.4,63.7) 53.4,65.959 54.595,67.154 68.5,67.154 69.25,67.904 J34.5@69.25,70
LCD_DATA22/SPI1_MOSI: J34.4 R210.1 U11.N19 | length 156.5
  Top w0.119: v1(19.5,62.75) R210.1@20.27,62.75 ; v1(72.6,31.4) 73.09,31.4 U11.N19@73.21,31.28
  Signal_8 w0.127: J34.4@68,70 68,69.1 68.296,68.804 78.046,68.804 80.22,66.63 80.22,62.961 80.37,62.811 80.37,61.089 82.435,59.024 87.194,59.024 89.214,57.004 90.022,57.004 90.754,56.272 90.753,56.271 90.753,55.717 93.937,52.534 93.937,51.009 93.008,50.08 93.008,48.904 93.217,48.694 93.217,43.921 92.825,43.529 92.825,42.971 93.571,42.224 93.571,40.682 94.274,39.979 94.274,37.026 93.006,35.757 93.006,26.146 89.205,22.346 83.795,22.346 83.246,22.895 83.246,27.654 82.771,28.129 82.705,28.129 82.178,28.656 80.449,28.656 79.876,29.229 78.705,29.229 78.32,29.614 78.32,29.674 78.074,29.921 73.65,29.921 73.546,30.024 72.276,30.024 72.03,30.271 72.03,30.83 v1(72.6,31.4)
  Signal_7 w0.127: v1(19.5,62.75) 20,63.25 20,69.691 20.773,70.464 37.151,70.464 39.305,68.309 43.209,68.309 45,70.1 59,70.1 61.3,67.8 67,67.8 68,68.8 J34.4@68,70
LCD_DATA23/SPI1_MISO: J34.3 R211.1 U11.N20 | length 154.9
  Top w0.119: v1(19.5,63.75) 19.75,64 R211.1@20.27,64 ; v1(72.575,30.495) 72.575,30.391 72.956,30.01 U11.N20@73.21,30.01
  Signal_8 w0.127: J34.3@66.75,70 66.75,69 67.2,68.55 77.941,68.55 79,67.491 79,64.565 79.27,64.295 79.27,61.83 82.33,58.77 87.089,58.77 89.109,56.75 89.917,56.75 90.499,56.168 90.499,55.612 93.683,52.429 93.683,51.114 92.754,50.185 92.754,48.799 92.963,48.589 92.963,47.163 92.571,46.771 92.571,42.865 93.283,42.154 93.283,40.611 94.02,39.874 94.02,39.163 93.35,38.493 93.35,36.973 92.752,36.375 92.752,26.252 89.1,22.6 83.9,22.6 83.5,23 83.5,28.75 82.87,29.38 82.87,29.595 82.595,29.87 82.205,29.87 81.937,29.602 80.793,29.602 80.674,29.72 79.545,29.72 79.095,30.17 78.454,30.17 77.725,30.9 77.275,30.9 77.185,30.81 76.19,30.81 76.129,30.87 74.905,30.87 74.896,30.862 72.942,30.862 v1(72.575,30.495)
  Signal_7 w0.127: v1(19.5,63.75) 18.976,64.274 18.976,69.476 20.218,70.718 38.227,70.718 40.045,68.9 43.3,68.9 44.754,70.354 59.746,70.354 61.9,68.2 66,68.2 66.75,68.95 J34.3@66.75,70
LCD_DRDY: J21.31 U11.A9 U25.G9 | length 122.3
  Top w0.119: v1(17.49,69) 17.976,68.514 J21.31@17.976,67.05 ; v2(40.7,65) 40.7,64.989 41.116,64.573 41.116,63.342 41.6,62.858 U25.G9@41.6,61.75 ; U11.A9@88.45,43.98 v1(89.085,44.615)
  Signal_8 w0.127: v2(40.7,65) 41.2,64.5 42,64.5 42.46,64.04 42.46,55.64 42.68,55.42 42.774,55.42 43.02,55.174 43.02,54.826 42.7,54.505 v2(42.7,52.9)
  Signal_7 w0.127: v1(17.49,69) 16.6,69 16,68.4 16,63 17.447,61.553 22.105,61.553 22.648,61.01 22.648,60.51 25.712,57.446 26.4,57.446 29.411,54.435 33.879,54.435 35.132,53.182 42.418,53.182 v2(42.7,52.9) 43.59,52.9 44.116,53.426 47.226,53.426 47.809,54.009 50.695,54.009 53.538,56.852 59.157,56.852 59.926,57.62 60.274,57.62 60.919,56.975 66.011,56.975 66.491,57.455 72.155,57.455 72.671,57.97 76.29,57.97 77.093,57.168 85.199,57.168 85.714,56.653 89.455,56.653 90.653,55.455 90.653,52.455 91.203,51.905 91.203,46.733 v1(89.085,44.615)
LCD_HSYNC: J21.29 U11.B21 U25.J9 | length 144.4
  Top w0.119: v1(18.5,69.011) 18.976,68.535 J21.29@18.976,67.05 ; U25.J9@42.9,61.75 43.861,61.75 43.9,61.711 v2(43.9,61.6) ; U11.B21@87.18,28.74 v1(87.815,28.105)
  Signal_3 w0.127: v1(18.5,69.011) 18.789,69.3 23.5,69.3 24.156,69.956 36.044,69.956 38.71,67.29 38.71,66.814 39.424,66.1 39.424,65.681 40.565,64.54 43.5,64.54 43.9,64.14 v2(43.9,61.6)
  Signal_8 w0.127: v2(41,66.75) 43.9,63.85 43.9,62.695 43.88,62.674 43.88,61.62 v2(43.9,61.6)
  Signal_7 w0.127: v2(41,66.75) 45.456,66.75 47.931,64.274 52.179,64.274 53.374,63.079 53.374,62.72 53.721,62.374 54.46,62.374 54.605,62.229 56.695,62.229 56.97,62.505 56.97,63.104 59.936,66.07 60.908,66.07 61.358,66.52 78.698,66.52 78.839,66.38 83.664,66.38 84.005,66.72 84.395,66.72 86.8,64.315 86.8,61.535 87.782,60.552 91.366,60.552 93.701,58.217 93.701,55.103 96.985,51.819 96.985,44.09 98.383,42.692 98.383,35.14 93.1,29.857 93.1,28.1 92.13,27.13 89.395,27.13 88.42,28.105 v1(87.815,28.105)
LCD_I2C_SCL: J21.33 J31.17 R103.2 | length 121.5
  Top w0.119: v1(15.937,69.533) 16.976,68.493 J21.33@16.976,67.05 ; v2(64,21.9) 64,22.32 64.1,22.42 R103.2@64,22.52
  Signal_3 w0.127: v1(15.937,69.533) 16.205,69.802 18.573,69.802 18.579,69.808 21.208,69.808 21.492,70.092 23.491,70.092 23.862,70.464 36.536,70.464 38.221,68.78 v1(39.5,68.78)
  Signal_8 w0.127: v1(39.5,68.78) 38.8,68.08 38.8,67.678 39.203,67.275 41.333,67.275 45.57,63.038 45.57,60.195 45.141,59.766 45.141,58.359 45.9,57.6 45.9,51.2 43.873,49.173 43.873,47.228 43.415,46.77 43.055,46.77 42.78,46.495 42.78,46.105 43.873,45.012 43.873,33.869 45.398,32.344 45.398,29.213 45.33,29.145 45.33,28.17 45.6,27.9 45.6,26 43.2,23.6 v1(43.2,18)
  Signal_7 w0.127: v1(43.2,18) 44,18 44.24,18.24 50.415,18.24 50.883,17.772 59.127,17.772 61.665,20.309 62.723,20.309 63.284,20.871 63.571,20.871 64,21.3 v2(64,21.9)
  Bottom w0.119: J31.17@31.351,65.2 31.351,67.151 31.74,67.54 32.67,67.54 33.429,68.3 39.02,68.3 v1(39.5,68.78)
LCD_I2C_SDA: J21.34 J31.18 R105.2 | length 100.5
  Top w0.119: J21.34@16.476,67.05 v1(16.476,68.007) ; v2(58.95,30.4) 59.109,30.241 59.109,29.081 59.116,29.073 59.116,28.727 59.077,28.687 59.077,28.324 59.448,27.952 60.549,27.952 61.299,27.202 63.238,27.202 64,26.44 R105.2@64,25.73
  Signal_3 w0.127: v1(16.476,68.007) 16.476,68.652 17.373,69.548 18.678,69.548 18.684,69.554 21.854,69.554 22.138,69.838 23.596,69.838 23.968,70.21 36.269,70.21 38.704,67.775 v1(39.475,67.775)
  Signal_8 w0.127: v1(39.475,67.775) 40.6,68.9 43.9,68.9 44.4,69.4 51,69.4 51.75,68.65 51.75,65.569 52.279,65.039 52.279,63.911 54.07,62.12 54.306,62.12 55.446,60.98 55.446,58.819 55.9,58.365 55.9,50.171 55.1,49.371 55.1,48.213 55.328,47.985 55.328,46.451 55.1,46.222 55.1,43.467 55.096,43.463 55.096,42.395 55.798,41.693 55.798,39.714 55.23,39.145 55.23,33.654 55.274,33.61 55.274,32.615 57.232,30.656 57.661,30.656 57.918,30.4 v2(58.95,30.4)
  Bottom w0.119: J31.18@32.601,65.2 32.601,66.801 33.6,67.8 39.45,67.8 v1(39.475,67.775)
LCD_IRQ_N: J21.35 J31.19 R78.2 R168.2 R270.2 | length 87.3
  Top w0.119: v2(15.4,68.9) 15.976,68.324 J21.35@15.976,67.05
  Signal_3 w0.127: v2(15.4,68.9) 16,68.3 16,67.548 16.547,67 33.135,67 33.405,67.271 34.579,67.271 v1(34.626,67.223)
  Signal_8 w0.127: v1(34.626,67.223) 34.626,65.974 35.6,65 35.6,59.7 34.9,59 34.9,56.945 35.221,56.624 35.221,55.655 35.2,55.635 35.2,52.7 36.1,51.8 v2(36.1,51.4)
  Signal_7 w0.127: v2(36.1,51.4) 36.335,51.4 36.756,50.979 42.767,50.979 43.021,50.725 47.594,50.725 48.539,51.67 50.017,51.67 50.275,51.412 50.275,51.1 50.879,50.496 54.296,50.496 57.7,53.9 60.635,53.9 62.115,55.38 65.454,55.38 66.584,54.25 66.831,54.25 67.306,53.775 69.1,53.775 69.6,54.275 69.6,54.435 69.529,54.505 69.529,55.229 v1(69.6,55.3)
  Bottom w0.119: R168.2@32.3,62.88 32.92,63.5 33.5,63.5 33.851,63.851 J31.19@33.851,65.2 33.851,66.323 v1@34.751,67.223 ; v1(34.626,67.223) v1@34.751,67.223 ; R270.2@68.48,53.5 R78.2@69.52,53.5 69.52,55.22 v1(69.6,55.3) ; v1@34.751,67.223 34.778,67.25 v1@34.752,67.223
LCD_RESET: J21.32 R259.1 U11.A19 | length 135.4
  Top w0.119: J21.32@17.476,67.05 v1(17.476,68.007) ; v1(27,61.75) 27,62.25 27.25,62.5 R259.1@27.77,62.5 ; U11.A19@88.45,31.28 89.17,32 v1(89.75,32)
  Signal_7 w0.127: v1(17.476,68.007) 17.476,63.924 19.2,62.2 21.566,62.2 21.595,62.228 23.172,62.228 23.854,61.546 26.22,61.546 26.425,61.75 v1(27,61.75) 28.026,60.724 28.026,57.649 28.875,56.8 34.465,56.8 35.221,56.045 35.221,55.914 36.685,54.45 42.65,54.45 43.2,55 44.2,55 46.46,57.26 46.46,60.26 48.625,62.425 52.326,62.425 53.539,61.211 57.477,61.211 58.571,62.305 58.571,62.655 61.673,65.758 76.99,65.758 77.718,65.03 78.273,65.03 78.721,65.478 83.305,65.478 86.038,62.746 86.038,61.219 87.467,59.79 91.051,59.79 92.939,57.902 92.939,54.787 96.223,51.504 96.223,43.775 97.621,42.376 97.621,37.271 96.87,36.52 96.87,34.705 94.736,32.57 91.005,32.57 90.435,32 v1(89.75,32) v1@89.797,31.953
LCD_VSYNC: J21.30 U11.A11 U25.H9 | length 118.3
  Top w0.119: J21.30@18.476,67.05 v1(18.476,68.007) ; U25.H9@42.25,61.75 42.8,62.3 42.9,62.2 v2(43.3,62.2) ; U11.A11@88.45,41.44 v1(89.085,42.075)
  Signal_8 w0.127: v2(43.3,62.2) 43.3,61.6 42.754,61.054 42.754,57.246 43.4,56.6 43.4,54.5 43.6,54.3 v2(43.6,53.7)
  Signal_7 w0.127: v1(18.476,68.007) 18.006,68.477 17.281,68.477 17.006,68.202 17.006,63.394 18.593,61.807 22.21,61.807 22.902,61.116 22.902,60.706 25.908,57.7 26.511,57.7 29.458,54.753 33.92,54.753 35.237,53.436 43.336,53.436 v2(43.6,53.7) 44.462,53.7 47.042,56.28 51.445,56.28 52.525,57.36 58.947,57.36 59.715,58.128 60.485,58.128 60.85,57.764 63.798,57.764 64.205,58.17 66.976,58.17 67.526,58.72 67.874,58.72 68.12,58.474 68.12,58.314 68.405,58.03 69.17,58.03 69.865,58.724 71,58.724 71.216,58.508 76.492,58.508 77.324,57.676 80.9,57.676 80.936,57.711 84.835,57.711 85.136,58.012 88.814,58.012 91.161,55.665 91.161,54.033 92.22,52.974 92.22,52.32 92.018,52.118 92.018,43.418 90.675,42.075 v1(89.085,42.075)
LDO4_1V8: C81.1 C82.1 C83.1 C84.1 C85.1 U11.D4 U25.C5 U25.C7 U25.D3 U25.G3 U25.G5 | length 76.3
  Top w0.125: U25.C7@39,60.45 38.675,60.125 38.675,59.475 U25.C5@39,59.15 v3(39.65,59.15) ; U25.D3@39.65,57.85 39.975,57.525 41.275,57.525 U25.G3@41.6,57.85 ; v3(40.95,59.15) U25.G5@41.6,59.15 ; U11.D4@84.64,50.33 v1(85.275,50.965)
  Top w0.25: U25.D3@39.65,57.85 39.818,58.018 39.85,58.018 40.3,58.468 v3(40.3,58.5)
  Signal_8 w0.5: v2(78.7,56.3) 79.407,55.593 83.006,55.593 83.343,55.256 83.343,55.228 83.392,55.179 83.392,52.551 83.348,52.507 83.348,51.963 83.392,51.919 83.392,51.908 83.894,51.406 84.834,51.406 v1(85.275,50.965)
  Signal_4 w0.5: v3(40.95,59.15) 41.6,59.15 41.9,59.45 41.9,63 42.3,63.4 42.3,64.029 42.828,64.557 43.286,64.557 49.054,70.325 54.375,70.325 57.5,67.2 70.7,67.2 73.5,64.4 73.5,60.3 74.939,58.861 76.439,58.861 78.7,56.6 v2(78.7,56.3)
  Bottom w0.25: C82.1@38.675,58.635 38.818,58.635 39.333,59.15 ; C81.1@38.675,59.665 38.818,59.665 39.333,59.15 ; v3(39.65,59.15) 39.333,59.15 ; C84.1@39.94,57.7 40.3,58.06 v3(40.3,58.5) ; v3(40.95,59.15) v3@40.98,59.15 ; C85.1@41.925,58.235 41.865,58.235 41.431,58.669 41.431,58.699 v3@40.98,59.15 ; C83.1@41.925,59.265 41.81,59.15 v3@40.98,59.15
LDOG: C55.1 U1.3 U11.E1 | length 48.6
  Top w0.119: U11.E1@83.37,54.14 83.73,54.5 v1(84.1,54.5)
  Signal_4 w0.127: v1(84.1,54.5) 84.1,54.6 84.745,55.246 85.47,55.246 86.029,54.686 86.029,35.971 86.85,35.15 87.85,35.15 88.6,34.4 88.6,27.765 88.77,27.595 88.77,27.07 85.9,24.2 85.9,22.921 87.121,21.7 88.378,21.7 91.7,18.379 v3(91.7,17.4)
  Bottom w0.119: v3(91.7,17.4) 92.36,17.4 C55.1@92.4,17.44 92.45,17.49 U1.3@93.55,17.49
LINE_IN_A_L: J26.4 L21.1 | length 2.2
  Top w0.125: L21.1@61.75,6.02 62.37,6.02 62.85,6.5 J26.4@63.75,6.5
LINE_IN_A_R: J26.3 L20.1 | length 2.9
  Top w0.125: L20.1@61.75,8.77 62.58,8.77 62.75,8.6 62.75,7.85 62.85,7.75 J26.3@63.75,7.75
LINE_IN_B_L: J33.6 L23.1 | length 3.6
  Top w0.119: J33.6@63.75,13.5 65.15,13.5 65.4,13.75 L23.1@67.27,13.75
LINE_IN_B_R: J33.5 L22.1 | length 3.5
  Top w0.119: J33.5@63.75,14.75 L22.1@67.27,14.75
LINE_OUT_L: J26.7 U6.23 | length 35.7
  Signal_3 w0.125: J26.7@63.75,2.75 68.05,2.75 68.575,2.225 70.581,2.225 73.804,5.448 80.148,5.448 81.9,7.2 81.9,13.181 79.581,15.5 77.906,15.5 77.209,16.197 76.803,16.197 76.2,16.8 v2(76.2,17.3)
  Bottom w0.125: v2(76.2,17.3) 76.22,17.32 76.22,18.86 U6.23@76.2,18.88
LINE_OUT_R: J26.6 U6.24 | length 35.8
  Signal_3 w0.125: J26.6@63.75,4 64.8,4 65.798,3.002 68.154,3.002 68.679,2.477 70.477,2.477 73.7,5.7 79.9,5.7 81.607,7.407 81.607,13.118 79.477,15.248 77.802,15.248 77.105,15.945 76.698,15.945 75.78,16.863 75.78,18.119 v2(75.754,18.146)
  Bottom w0.125: v2(75.754,18.146) 75.8,18.1 U6.24@75.8,18.88
LTE_PRI: J13.9 U11.D13 | length 25
  Top w0.119: U11.D13@84.64,38.9 v1(85.275,38.265)
  Signal_3 w0.127: v2(93.5,43.25) 93.824,43.575 93.824,50.146 94.325,50.647 94.325,52.2 96.375,54.25 J13.9@97.75,54.25
  Signal_7 w0.127: v1(85.275,38.265) 85.275,38.675 88.1,41.5 91.75,41.5 v2(93.5,43.25)
LTE_SYNC: J13.11 U11.D14 | length 27.6
  Top w0.119: U11.D14@84.64,37.63 v1(85.275,36.995)
  Signal_3 w0.127: v2(94.5,42.5) 95.17,43.17 95.17,49.313 95.353,49.495 95.353,50.703 96.4,51.75 J13.11@97.75,51.75
  Signal_7 w0.127: v1(85.275,36.995) 85.87,36.4 88.1,36.4 88.997,37.297 91.72,37.297 91.895,37.122 94.18,37.122 94.8,37.742 94.8,40.246 94.496,40.55 94.496,42.496 v2(94.5,42.5)
LVDS0_CLK_N: L32.1 U25.B4 | length 17.2
  Top w0.102: v2(37.1,59.2) 37.1,59.131 37.426,58.805 37.826,58.805 38.131,58.5 U25.B4@38.35,58.5
  Signal_3 w0.127: v1(24,60.5) 24.335,60.165 24.335,59.763 24.728,59.37 26.23,59.37 26.651,58.949 27.842,58.949 28.162,59.27 35.725,59.27 36.191,58.804 36.704,58.804 v2(37.1,59.2)
  Bottom w0.102: v1(24,60.5) 24.225,60.725 L32.1@24.225,61.6
LVDS0_CLK_P: L32.4 U25.A4 | length 15.9
  Top w0.102: v2(36.4,59.3) 36.4,59.216 36.9,58.716 37.084,58.716 37.3,58.5 U25.A4@37.7,58.5
  Signal_3 w0.127: v1(25,60.5) 24.665,60.165 24.665,59.9 24.865,59.7 26.367,59.7 26.787,59.279 27.705,59.279 28.025,59.6 35.861,59.6 36.241,59.22 36.32,59.22 v2(36.4,59.3)
  Bottom w0.102: L32.4@24.775,61.6 24.775,60.725 v1(25,60.5)
LVDS0_TX0_N: L5.1 U25.B1 | length 35.1
  Top w0.102: v2(37.9,55.9) 38.299,56.299 38.299,56.499 U25.B1@38.35,56.55
  Signal_3 w0.127: v1(12.75,60) 13.195,60.445 13.195,61.037 13.588,61.43 14.537,61.43 14.83,61.137 14.83,60.295 ; 14.83,60.295 14.83,59.905 14.83,58.407 15.6,57.637 15.6,56.192 16.692,55.1 20.4,55.1 21.433,56.133 27.867,56.133 28.675,56.942 30.137,56.942 30.349,56.73 37.422,56.73 37.715,56.437 37.715,56.085 v2(37.9,55.9)
  Bottom w0.102: v1(12.75,60) 12.975,60.225 L5.1@12.975,61.6
LVDS0_TX0_P: L5.4 U25.A1 | length 34.1
  Top w0.102: v2(37.2,55.9) 37.649,56.349 37.649,56.499 U25.A1@37.7,56.55
  Signal_3 w0.127: v1(13.811,59.945) 13.525,60.231 13.525,60.9 13.725,61.1 14.4,61.1 14.5,61.001 14.5,59.768 ; 14.5,59.768 14.5,58.27 15.27,57.5 15.27,56.055 16.555,54.77 20.537,54.77 21.57,55.803 28.003,55.803 28.812,56.612 30.001,56.612 30.212,56.4 37.285,56.4 37.385,56.3 37.385,56.085 v2(37.2,55.9)
  Bottom w0.102: L5.4@13.525,61.6 13.525,60.231 v1(13.811,59.945)
LVDS0_TX1_N: L30.1 U25.B2 | length 26.4
  Top w0.102: v2(35.9,57.2) 35.916,57.2 36.4,57.684 36.8,57.684 36.979,57.505 37.826,57.505 38.131,57.2 U25.B2@38.35,57.2
  Signal_3 w0.127: v1(16.5,60) 16.87,59.63 16.87,58.73 19.03,56.57 27.437,56.57 28.333,57.467 30.442,57.467 30.708,57.2 v2(35.9,57.2)
  Bottom w0.102: v1(16.5,60) 16.725,60.225 L30.1@16.725,61.6
LVDS0_TX1_P: L30.4 U25.A2 | length 25
  Top w0.102: v2(36.6,57.2) U25.A2@37.7,57.2
  Signal_3 w0.127: v1(17.5,60) 17.2,59.7 17.2,58.867 19.167,56.9 27.3,56.9 28.197,57.797 30.578,57.797 30.845,57.53 35.528,57.53 35.694,57.696 36.106,57.696 36.6,57.202 v2(36.6,57.2)
  Bottom w0.102: L30.4@17.275,61.6 17.275,60.225 v1(17.5,60)
LVDS0_TX2_N: L31.1 U25.B3 | length 26.1
  Top w0.102: v2(35.6,58.8) 35.795,58.605 36.426,58.605 36.813,58.218 37.022,58.218 37.085,58.155 37.826,58.155 38.131,57.85 U25.B3@38.35,57.85
  Signal_3 w0.127: v1(20.25,60.5) 20.6,60.85 20.6,61.4 20.242,61.758 19.8,61.758 19.1,61.058 19.1,59.917 20.062,58.955 22.787,58.955 23.784,57.958 27.008,57.958 27.673,58.623 35.423,58.623 v2(35.6,58.8)
  Bottom w0.102: v1(20.25,60.5) 20.475,60.725 L31.1@20.475,61.6
LVDS0_TX2_P: L31.4 U25.A3 | length 27
  Top w0.102: v2(35.6,58.117) 35.783,58.3 36.3,58.3 36.687,57.913 36.895,57.913 36.958,57.85 U25.A3@37.7,57.85
  Signal_3 w0.127: v1(21.25,60.5) 20.93,60.82 20.93,61.537 20.379,62.088 19.663,62.088 18.77,61.195 18.77,59.78 19.925,58.625 22.65,58.625 23.647,57.628 27.145,57.628 27.81,58.293 35.423,58.293 v2(35.6,58.117)
  Bottom w0.102: L31.4@21.025,61.6 21.025,60.725 v1(21.25,60.5)
LVDS0_TX3_N: L33.1 U25.B5 | length 19
  Top w0.102: v2(37.1,60.3) 37.2,60.3 37.397,60.103 37.825,60.103 38.003,59.925 38.003,59.497 U25.B5@38.35,59.15
  Signal_3 w0.127: v1@27.753,60.503 28.07,60.82 28.07,63.937 29.363,65.23 32.872,65.23 36.865,61.237 36.865,60.535 v2(37.1,60.3)
  Bottom w0.102: v1(27.551,60.503) 27.753,60.503 27.975,60.725 L33.1@27.975,61.6
LVDS0_TX3_P: L33.4 U25.A5 | length 17.6
  Top w0.102: v2(36.3,60.3) 36.416,60.3 36.9,59.816 37.061,59.816 37.508,59.369 37.508,59.342 U25.A5@37.7,59.15
  Signal_3 w0.127: v1(28.75,60.5) 28.4,60.85 28.4,63.8 29.5,64.9 32.735,64.9 36.535,61.1 36.535,60.535 v2(36.3,60.3)
  Bottom w0.102: L33.4@28.525,61.6 28.525,60.725 v1(28.75,60.5)
LVDS_6B8B: R171.1 R176.2 U25.F7 | length 9.7
  Top w0.119: R171.1@37,67.58 R176.2@38.534,67.58 39.042,67.072 39.042,66.269 39.9,65.41 39.9,62.754 40.625,62.029 40.625,60.775 U25.F7@40.95,60.45
LVDS_FLIP: R173.1 R178.2 R249.2 U25.C2 | length 5.5
  Top w0.119: R249.2@36.7,54.38 R178.2@37.9,54.38 39.059,54.38 39.084,54.355 39.084,54.927 38.689,55.322 38.689,56.889 U25.C2@39,57.2
LVDS_MAP: R172.1 R177.2 U25.E8 | length 5.2
  Top w0.119: R177.2@39.2,64.02 R172.1@38.1,64.02 38.1,63.4 39.325,62.175 39.325,61.635 39.549,61.411 39.779,61.411 40.09,61.1 U25.E8@40.3,61.1
LVDS_PD#/IO30: R266.2 U25.D8 U27.40 | length 67.5
  Top w0.119: R266.2@37,64.02 v2(37,63.3) 37.5,62.8 38.05,62.8 38.689,62.161 38.689,61.621 38.899,61.411 39.129,61.411 39.44,61.1 U25.D8@39.65,61.1 ; U27.40@55.45,31 56.2,31 v3(56.4,30.8)
  Signal_3 w0.127: v2(37,63.3) 38,62.3 38,57.4 38.5,56.9 38.5,56.354 38.488,56.342 38.488,54.768 39.056,54.2 44.616,54.2 46.46,56.044 46.46,59.06 46.72,59.32 49.726,59.32 50.326,59.92 51.424,59.92 51.82,59.524 v3(53.324,59.524)
  Signal_8 w0.127: v3(53.324,59.524) 53.324,58.959 53.578,58.705 53.578,56.14 54.8,54.918 54.8,52.535 54.345,52.079 53.385,52.079 52.58,51.274 52.58,49.326 53.08,48.825 53.55,48.825 54.101,48.274 54.679,48.274 55.074,47.879 55.074,46.556 54.846,46.328 54.846,44.262 54.725,44.141 54.725,41.225 54.976,40.975 54.976,32.224 v3(56.4,30.8)
LVDS_RF: R170.1 R175.2 R248.2 U25.G8 | length 8.4
  Top w0.119: U25.G8@41.6,61.1 41.939,61.439 41.939,62.281 42.758,63.1 v2(43.4,63.1)
  Bottom w0.119: R170.1@41.48,62.1 42.48,62.1 R175.2@42.5,62.08 42.5,62.089 43.4,62.989 v2(43.4,63.1) 43.9,62.6 44.7,62.6 45,62.9 R248.2@45.92,62.9
LVDS_RS: R169.1 R174.2 U25.F8 | length 5.2
  Top w0.119: v2(40.7,63.7) 40.7,63.41 41.275,62.835 41.275,61.425 U25.F8@40.95,61.1
  Bottom w0.119: R174.2@38.475,63.68 38.495,63.7 v2(40.7,63.7)
MCA_CLKOUT32K: R81.1 U11.C4 | length 7.4
  Top w0.119: U11.C4@85.91,50.33 v1(86.545,50.965)
  Bottom w0.119: R81.1@84.75,56.25 84.75,52 85,51.75 85.76,51.75 v1(86.545,50.965)
MCA_IO1: J30.7 R201.1 U11.B2 | length 149.5
  Top w0.119: U11.B2@87.18,52.87 v1(87.815,52.235)
  Signal_3 w0.127: v2(3.6,64.6) 4,65 8.4,65 13.456,70.056 18.214,70.056 18.504,70.346 23.386,70.346 23.757,70.718 38.382,70.718 40.2,68.9 40.2,67.7 39.904,67.405 39.904,66.601 40.805,65.7 v2(47.9,65.7) 48.196,65.996 48.955,65.996 49.505,66.546 55.305,66.546 56.046,67.286 75.786,67.286 76.7,68.2 77.785,68.2 77.805,68.22 80.97,68.22 83.411,65.78 86.814,65.78 88.255,67.221 88.645,67.221 90.919,64.946 90.919,53.776 89.378,52.235 v1(87.815,52.235)
  Signal_8 w0.127: J30.7@2,34.75 3.15,34.75 3.904,35.504 3.904,43.103 5.5,44.699 5.5,48.1 7.046,49.646 7.732,49.646 8.495,50.409 8.495,53.255 6.9,54.85 6.9,58.3 3.6,61.6 v2(3.6,64.6)
  Bottom w0.119: R201.1@47.18,65.7 v2(47.9,65.7)
MCA_IO2/EXT_VREF: R181.1 U11.B5 | length 114.7
  Top w0.125: v1(17.456,29.063) 17.619,28.9 18.976,28.9 19.1,28.776 R181.1@19.1,28.56 ; U11.B5@87.18,49.06 87.19,49.06 v1(87.8,48.45)
  Signal_8 w0.125: v1(17.456,29.063) 18.1,29.706 18.1,34.3 20.494,36.694 20.494,43.694 22.6,45.8 22.6,48.5 22.069,49.031 22.069,53.031 22.12,53.082 22.12,57.369 v1(22.25,57.5)
  Signal_7 w0.125: v1(22.25,57.5) 23.15,56.6 26.1,56.6 29.024,53.676 33.274,53.676 34.953,51.997 36.203,51.997 36.747,51.453 39.603,51.453 40,51.85 46.75,51.85 48.15,53.25 51.1,53.25 53.9,56.05 61.05,56.05 61.2,56.2 66.5,56.2 66.95,56.65 73.7,56.65 74.8,55.55 83.35,55.55 83.75,55.95 83.786,55.95 83.806,55.97 84.214,55.97 84.214,55.95 85,55.95 85.85,55.1 86.75,55.1 87.269,54.581 87.269,50.881 89,49.15 89.55,49.15 89.8,48.9 89.8,48.15 89.55,47.9 88.35,47.9 v1(87.8,48.45)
